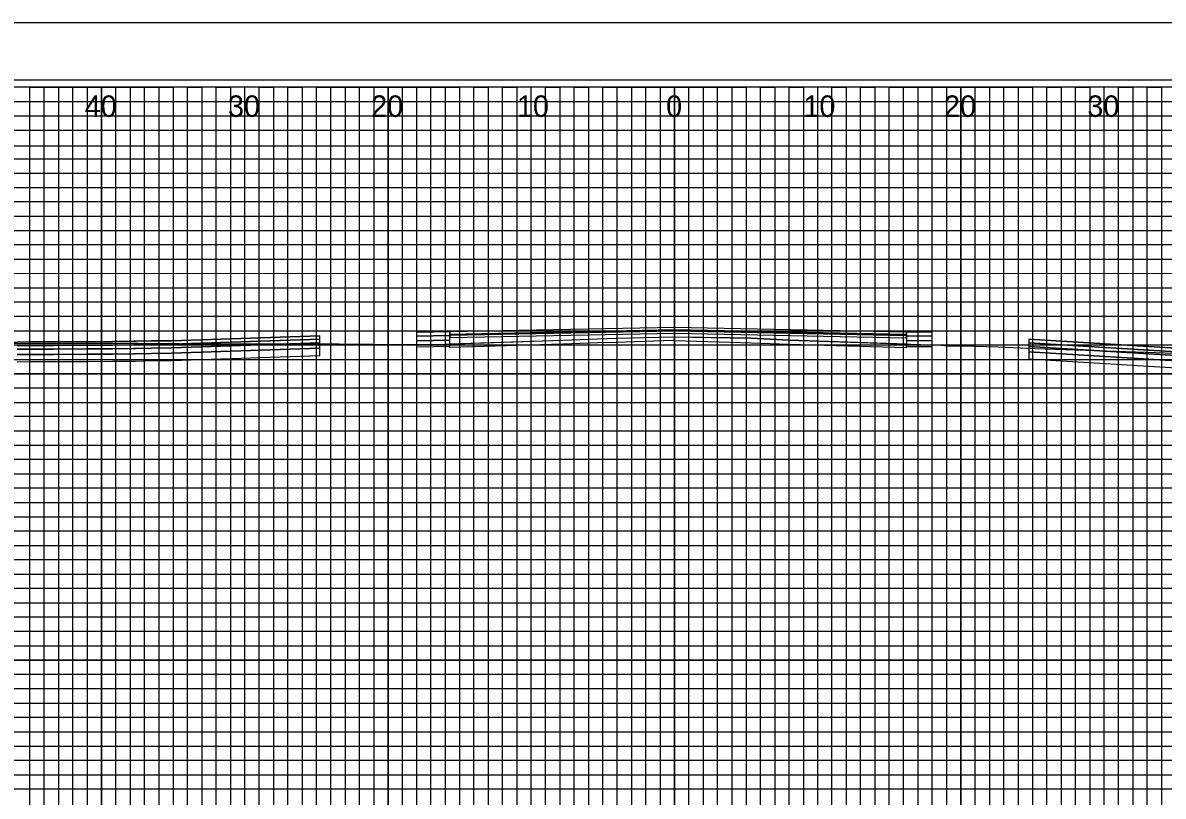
# Model space of a CAD drawing. Extents: x -13 to 760, y -5 to 1491.
# Drawn here: x 114.5 to 194.1, y 1436.5 to 1490.5 of the extents above; entities that cross this region are included whole.
import ezdxf

# ---------------------------------------------------------------- set-up
doc = ezdxf.new("R2010")
doc.units = 0
for name, color, linetype in [('Exist XS Ground Line', 7, 'Continuous'), ('Prop CMT Concrete Structures', 7, 'Continuous'), ('Prop CMT Pvmt Course 1', 7, 'Continuous'), ('Prop CMT Pvmt Course 2', 7, 'Continuous'), ('Prop CMT Pvmt Course 3', 7, 'Continuous'), ('Prop CMT Pvmt Course 4', 7, 'Continuous'), ('Prop CMT Subgrade Earthwork', 7, 'Continuous'), ('Prop Corridor Mesh Bottom', 7, 'Continuous'), ('Prop XS Offset Labels', 7, 'Continuous'), ('Scratch_Level_6', 7, 'Continuous'), ('Scratch_Level_9', 7, 'Continuous'), ('Sheet Cross Section CELL', 7, 'Continuous'), ('Sheet Cross Section Grid Major CELL', 7, 'Continuous'), ('Sheet Cross Section Grid Middle CELL', 7, 'Continuous'), ('Sheet Cross Section Grid Minor 1 CELL', 7, 'Continuous'), ('Sheet Cross Section Grid Minor 2 CELL', 7, 'Continuous'), ('Sheet Cutting Line CELL', 7, 'Continuous'), ('Sheet DOT Grid CELL', 7, 'Continuous'), ('Sheet Plot Border Inside CELL', 7, 'Continuous'), ('Sheet Plot Border Outside CELL', 7, 'Continuous')]:
    doc.layers.add(name, color=color, linetype=linetype)

msp = doc.modelspace()

# ---------------------------------------------------------------- linework, layer by layer
at = {"layer": 'Exist XS Ground Line'}
msp.add_lwpolyline([(106.336, 1468.112), (118.955, 1468.147), (122.535, 1468.157), (128.384, 1468.107), (132.28, 1468.115), (133.801, 1468.109), (136.596, 1468.114), (141.303, 1468.066), (143.958, 1468.089), (152.205, 1468.367), (154.623, 1468.457), (155.921, 1468.491), (159.879, 1468.583), (163.881, 1468.525), (165.361, 1468.5), (168.016, 1468.365), (178.623, 1468.013), (179.044, 1467.964), (180.183, 1467.974), (182.593, 1467.894), (185.157, 1467.784), (190.145, 1467.622), (197.718, 1467.361)], dxfattribs=at)
msp.add_lwpolyline([(106.336, 1468.112), (118.955, 1468.147), (122.535, 1468.157), (128.384, 1468.107), (132.28, 1468.115), (133.801, 1468.109), (136.596, 1468.114), (141.303, 1468.066), (143.958, 1468.089), (152.205, 1468.367), (154.623, 1468.457), (155.921, 1468.491), (159.879, 1468.583), (163.881, 1468.525), (165.361, 1468.5), (168.016, 1468.365), (178.623, 1468.013), (179.044, 1467.964), (180.183, 1467.974), (182.593, 1467.894), (185.157, 1467.784), (190.145, 1467.622), (197.718, 1467.361)], dxfattribs=at)
at = {"layer": 'Prop CMT Pvmt Course 1'}
for points in [[(144.313, 1468.934), (144.313, 1468.768), (160, 1469.082), (160, 1469.082), (176.202, 1468.757), (176.202, 1468.757), (176.202, 1468.924), (176.202, 1468.924), (176.202, 1468.924), (160, 1469.248), (160, 1469.248), (144.313, 1468.934), (144.313, 1468.934)], [(114.117, 1467.98), (114.991, 1467.985), (116.643, 1467.993), (119.029, 1468.005), (120.751, 1468.017), (122.259, 1468.03), (122.363, 1468.031), (123.49, 1468.056), (124.885, 1468.073), (135.25, 1468.425), (135.25, 1468.425), (135.25, 1468.425), (135.25, 1468.675), (135.25, 1468.675), (135.25, 1468.675), (124.885, 1468.323), (123.49, 1468.306), (122.363, 1468.281), (122.259, 1468.28), (120.751, 1468.267), (119.029, 1468.255), (116.643, 1468.243), (114.991, 1468.235), (114.117, 1468.23)], [(144.313, 1468.934), (142, 1468.888), (142, 1468.888), (142, 1468.638), (144.313, 1468.684), (144.313, 1468.684), (144.313, 1468.934), (144.313, 1468.934), (144.313, 1468.934)], [(178, 1468.888), (176.202, 1468.924), (176.202, 1468.924), (176.202, 1468.674), (178, 1468.638), (178, 1468.638), (178, 1468.888), (178, 1468.888), (178, 1468.888)], [(184.75, 1468.43), (184.75, 1468.18), (184.75, 1468.18), (184.75, 1468.18), (196.182, 1467.475)], [(196.182, 1467.725), (184.75, 1468.43), (184.75, 1468.43), (184.75, 1468.43)]]:
    msp.add_lwpolyline(points, dxfattribs=at)
at = {"layer": 'Prop CMT Pvmt Course 2'}
for points in [[(144.313, 1468.768), (144.313, 1468.705), (160, 1469.019), (160, 1469.019), (176.202, 1468.695), (176.202, 1468.695), (176.202, 1468.757), (176.202, 1468.757), (176.202, 1468.757), (160, 1469.082), (160, 1469.082), (144.313, 1468.768), (144.313, 1468.768)], [(114.117, 1467.73), (114.991, 1467.735), (116.643, 1467.743), (119.029, 1467.755), (120.751, 1467.767), (122.259, 1467.78), (122.363, 1467.781), (123.49, 1467.806), (124.885, 1467.823), (135.25, 1468.175), (135.25, 1468.175), (135.25, 1468.175), (135.25, 1468.425), (135.25, 1468.425), (135.25, 1468.425), (124.885, 1468.073), (123.49, 1468.056), (122.363, 1468.031), (122.259, 1468.03), (120.751, 1468.017), (119.029, 1468.005), (116.643, 1467.993), (114.991, 1467.985), (114.117, 1467.98)], [(144.313, 1468.684), (142, 1468.638), (142, 1468.638), (142, 1468.305), (144.313, 1468.351), (144.313, 1468.351), (144.313, 1468.684), (144.313, 1468.684), (144.313, 1468.684)], [(178, 1468.638), (176.202, 1468.674), (176.202, 1468.674), (176.202, 1468.341), (178, 1468.305), (178, 1468.305), (178, 1468.638), (178, 1468.638), (178, 1468.638)], [(184.75, 1468.18), (184.75, 1467.93), (184.75, 1467.93), (184.75, 1467.93), (196.182, 1467.225)], [(196.182, 1467.475), (184.75, 1468.18), (184.75, 1468.18), (184.75, 1468.18)]]:
    msp.add_lwpolyline(points, dxfattribs=at)
at = {"layer": 'Prop CMT Pvmt Course 3'}
for points in [[(144.313, 1468.351), (142, 1468.305), (142, 1468.305), (142, 1467.889), (144.313, 1467.934), (144.313, 1467.934), (144.313, 1468.351), (144.313, 1468.351), (144.313, 1468.351)], [(144.313, 1468.705), (144.313, 1468.539), (160, 1468.852), (160, 1468.852), (176.202, 1468.528), (176.202, 1468.528), (176.202, 1468.695), (176.202, 1468.695), (176.202, 1468.695), (160, 1469.019), (160, 1469.019), (144.313, 1468.705), (144.313, 1468.705)], [(178, 1468.305), (176.202, 1468.341), (176.202, 1468.341), (176.202, 1467.924), (178, 1467.888), (178, 1467.888), (178, 1468.305), (178, 1468.305), (178, 1468.305)], [(114.117, 1467.355), (114.991, 1467.36), (116.643, 1467.368), (119.029, 1467.38), (120.751, 1467.392), (122.259, 1467.405), (122.363, 1467.406), (123.49, 1467.431), (124.885, 1467.448), (135.25, 1467.8), (135.25, 1467.8), (135.25, 1467.8), (135.25, 1468.175), (135.25, 1468.175), (135.25, 1468.175), (124.885, 1467.823), (123.49, 1467.806), (122.363, 1467.781), (122.259, 1467.78), (120.751, 1467.767), (119.029, 1467.755), (116.643, 1467.743), (114.991, 1467.735), (114.117, 1467.73)], [(184.75, 1467.93), (184.75, 1467.555), (184.75, 1467.555), (184.75, 1467.555), (196.182, 1466.85)], [(196.182, 1467.225), (184.75, 1467.93), (184.75, 1467.93), (184.75, 1467.93)]]:
    msp.add_lwpolyline(points, dxfattribs=at)
at = {"layer": 'Prop CMT Pvmt Course 4'}
for points in [[(114.117, 1466.855), (114.991, 1466.86), (116.643, 1466.868), (119.029, 1466.88), (120.751, 1466.892), (122.259, 1466.905), (122.363, 1466.906), (123.49, 1466.931), (124.885, 1466.948), (135.25, 1467.3), (135.25, 1467.3), (135.25, 1467.3), (135.25, 1467.8), (135.25, 1467.8), (135.25, 1467.8), (124.885, 1467.448), (123.49, 1467.431), (122.363, 1467.406), (122.259, 1467.405), (120.751, 1467.392), (119.029, 1467.38), (116.643, 1467.368), (114.991, 1467.36), (114.117, 1467.355)], [(184.75, 1467.555), (184.75, 1467.055), (184.75, 1467.055), (184.75, 1467.055), (196.182, 1466.35)], [(196.182, 1466.85), (184.75, 1467.555), (184.75, 1467.555), (184.75, 1467.555)]]:
    msp.add_lwpolyline(points, dxfattribs=at)
at = {"layer": 'Prop CMT Subgrade Earthwork'}
for points in [[(142, 1467.889), (144.313, 1467.934), (144.313, 1467.934)], [(178, 1467.888), (178, 1467.888), (176.202, 1467.924)]]:
    msp.add_lwpolyline(points, dxfattribs=at)
at = {"layer": 'Prop Corridor Mesh Bottom'}
for points in [[(159.879, 1468.583), (160, 1468.581), (160, 1468.581), (160, 1468.331), (159.879, 1468.327), (159.879, 1468.327), (155.921, 1468.206), (155.921, 1468.206), (154.623, 1468.166), (152.205, 1468.092), (152.205, 1468.092), (144.313, 1467.851), (144.313, 1467.851), (144.313, 1468.101), (144.313, 1468.101), (144.313, 1468.101), (152.205, 1468.367), (152.205, 1468.367), (154.623, 1468.457), (155.921, 1468.491), (155.921, 1468.491), (159.879, 1468.583), (159.879, 1468.583)], [(176.202, 1468.093), (168.016, 1468.365), (168.016, 1468.365), (165.361, 1468.5), (165.361, 1468.5), (163.881, 1468.526), (163.881, 1468.526), (160, 1468.581), (160, 1468.581), (160, 1468.581), (160, 1468.331), (160, 1468.331), (163.881, 1468.214), (163.881, 1468.214), (165.361, 1468.17), (165.361, 1468.17), (168.016, 1468.09), (168.016, 1468.09), (176.202, 1467.843), (176.202, 1467.843), (176.202, 1468.093), (176.202, 1468.093), (176.202, 1468.093)]]:
    msp.add_lwpolyline(points, dxfattribs=at)
at = {"layer": 'Scratch_Level_6'}
for points in [[(97.758, 1468.16), (101.906, 1468.181), (103.95, 1468.191), (104.095, 1468.192), (104.974, 1468.196), (108.436, 1468.213), (110.661, 1468.225), (112.404, 1468.226), (114.117, 1468.23), (114.991, 1468.235), (116.643, 1468.243), (119.029, 1468.255), (120.751, 1468.267), (122.259, 1468.28), (122.363, 1468.281), (123.49, 1468.306), (124.885, 1468.323), (135.25, 1468.675)], [(184.75, 1468.43), (184.75, 1468.43), (196.182, 1467.725)]]:
    msp.add_lwpolyline(points, dxfattribs=at)
at = {"layer": 'Sheet Cross Section CELL'}
msp.add_lwpolyline([(320, 1486.02), (0, 1486.02), (0, 1276.02), (320, 1276.02)], close=True, dxfattribs=at)
at = {"layer": 'Sheet Cross Section Grid Major CELL'}
for p, q in [((130, 1486.02), (120, 1486.02)), ((120, 1486.02), (120, 1276.02)), ((130, 1276.02), (130, 1486.02)), ((150, 1486.02), (140, 1486.02)), ((140, 1486.02), (140, 1276.02)), ((150, 1276.02), (150, 1486.02)), ((170, 1486.02), (160, 1486.02)), ((160, 1486.02), (160, 1276.02)), ((170, 1276.02), (170, 1486.02)), ((190, 1486.02), (180, 1486.02)), ((180, 1486.02), (180, 1276.02)), ((190, 1276.02), (190, 1486.02))]:
    msp.add_line(p, q, dxfattribs=at)
for points in [[(0, 1476.02), (320, 1476.02), (320, 1466.02), (0, 1466.02)], [(0, 1456.02), (320, 1456.02), (320, 1446.02), (0, 1446.02)]]:
    msp.add_lwpolyline(points, dxfattribs=at)
at = {"layer": 'Sheet Cross Section Grid Middle CELL'}
for points in [[(115, 1276.02), (115, 1486.02), (125, 1486.02), (125, 1276.02)], [(135, 1276.02), (135, 1486.02), (145, 1486.02), (145, 1276.02)], [(155, 1276.02), (155, 1486.02), (165, 1486.02), (165, 1276.02)], [(175, 1276.02), (175, 1486.02), (185, 1486.02), (185, 1276.02)], [(0, 1481.02), (275, 1481.02)], [(0, 1461.02), (320, 1461.02), (320, 1471.02), (0, 1471.02)], [(0, 1441.02), (320, 1441.02), (320, 1451.02), (0, 1451.02)]]:
    msp.add_lwpolyline(points, dxfattribs=at)
at = {"layer": 'Sheet Cross Section Grid Minor 1 CELL'}
for p, q in [((0, 1485.02), (260, 1485.02)), ((260, 1484), (0, 1484)), ((0, 1483.02), (260, 1483.02)), ((260, 1481.91), (0, 1481.91)), ((0, 1480.02), (320, 1480.02))]:
    msp.add_line(p, q, dxfattribs=at)
for points in [[(0, 1479.02), (270, 1479.02), (320, 1479.02), (320, 1478.02), (0, 1478.02)], [(0, 1477.02), (320, 1477.02), (320, 1475.02), (0, 1475.02)], [(0, 1474.02), (320, 1474.02), (320, 1473.02), (0, 1473)], [(0, 1472.02), (320, 1472.02), (320, 1470.02), (0, 1470.02)], [(0, 1469.02), (320, 1469.02), (320, 1468.02), (0, 1468.02)], [(0, 1467.02), (320, 1467.02), (320, 1465.02), (0, 1465.02)], [(0, 1464.02), (320, 1464.02), (320, 1463.02), (0, 1463.02)], [(0, 1462.02), (320, 1462.02), (320, 1460.02), (0, 1460.02)], [(0, 1459.02), (320, 1459.02), (320, 1458.02), (0, 1458.02)], [(0, 1457.02), (320, 1457.02), (320, 1455.02), (0, 1455.02)], [(0, 1454.02), (320, 1454.02), (320, 1453.02), (0, 1453.02)], [(0, 1452.02), (320, 1452.02), (320, 1449.97), (320, 1449.02), (320, 1448.02), (0, 1448.02)], [(0, 1450.02), (320, 1450.02), (320, 1449.02), (0, 1449.02)], [(0, 1447.02), (320, 1447.02), (320, 1445.02), (0, 1445.05)], [(0, 1445.05), (320, 1445.02), (320, 1444.02), (0, 1444.02)], [(0, 1443.02), (320, 1443.02), (320, 1442.02), (0, 1442.02)], [(0, 1440.02), (320, 1440.02), (320, 1439.02), (0, 1439.02)], [(0, 1438.02), (320, 1438.02), (320, 1437.02), (0, 1437.02)]]:
    msp.add_lwpolyline(points, dxfattribs=at)
at = {"layer": 'Sheet Cross Section Grid Minor 2 CELL'}
for points in [[(115, 1276.02), (116, 1276.02), (116, 1486.02), (117, 1486.02), (117, 1276.02)], [(117, 1276.02), (118, 1276.02), (118, 1486.02), (119, 1486.02), (119, 1276.02)], [(120, 1276.02), (121, 1276.02), (121, 1486.02), (122, 1486.02), (122, 1276.02)], [(122, 1276.02), (123, 1276.02), (123, 1486.02), (124, 1486.02), (124, 1276.02)], [(125, 1276.02), (126, 1276.02), (126, 1486.02), (127, 1486.02), (127, 1276.02)], [(127, 1276.02), (128, 1276.02), (128, 1486.02), (129, 1486.02), (129, 1276.02)], [(130, 1276.02), (131, 1276.02), (131, 1486.02), (132, 1486.02), (132, 1276.02)], [(132, 1276.02), (133, 1276.02), (133, 1486.02), (134, 1486.02), (134, 1276.02)], [(135, 1276.02), (136, 1276.02), (136, 1486.02), (137, 1486.02), (137, 1276.02)], [(137, 1276.02), (138, 1276.02), (138, 1486.02), (139, 1486.02), (139, 1276.02)], [(140, 1276.02), (141, 1276.02), (141, 1486.02), (142, 1486.02), (142, 1276.02)], [(142, 1276.02), (143, 1276.02), (143, 1486.02), (144, 1486.02), (144, 1276.02)], [(145, 1276.02), (146, 1276.02), (146, 1486.02), (147, 1486.02), (147, 1276.02)], [(147, 1276.02), (148, 1276.02), (148, 1486.02), (149, 1486.02), (149, 1276.02)], [(150, 1276.02), (151, 1276.02), (151, 1486.02), (152, 1486.02), (152, 1276.02)], [(152, 1276.02), (153, 1276.02), (153, 1486.02), (154, 1486.02), (154, 1276.02)], [(155, 1276.02), (156, 1276.02), (156, 1486.02), (157, 1486.02), (157, 1276.02)], [(157, 1276.02), (158, 1276.02), (158, 1486.02), (159, 1486.02), (159, 1276.02)], [(160, 1276.02), (161, 1276.02), (161, 1486.02), (162, 1486.02), (162, 1276.02)], [(162, 1276.02), (163, 1276.02), (163, 1486.02), (164, 1486.02), (164, 1276.02)], [(165, 1276.02), (166, 1276.02), (166, 1486.02), (167, 1486.02), (167, 1276.02)], [(167, 1276.02), (168, 1276.02), (168, 1486.02), (169, 1486.02), (169, 1276.02)], [(170, 1276.02), (171, 1276.02), (171, 1486.02), (172, 1486.02), (172, 1276.02)], [(172, 1276.02), (173, 1276.02), (173, 1486.02), (174, 1486.02), (174, 1276.02)], [(175, 1276.02), (176, 1276.02), (176, 1486.02), (177, 1486.02), (177, 1276.02)], [(177, 1276.02), (178, 1276.02), (178, 1486.02), (179, 1486.02), (179, 1276.02)], [(180, 1276.02), (181, 1276.02), (181, 1486.02), (182, 1486.02), (182, 1276.02)], [(182, 1276.02), (183, 1276.02), (183, 1486.02), (184, 1486.02), (184, 1276.02)], [(185, 1276.02), (186, 1276.02), (186, 1486.02), (187, 1486.02), (187, 1276.02)], [(187, 1276.02), (188, 1276.02), (188, 1486.02), (189, 1486.02), (189, 1276.02)], [(190, 1276.02), (191, 1276.02), (191, 1486.02), (192, 1486.02), (192, 1276.02)], [(192, 1276.02), (193, 1276.02), (193, 1486.02), (194, 1486.02), (194, 1276.02)]]:
    msp.add_lwpolyline(points, dxfattribs=at)
at = {"layer": 'Sheet Cutting Line CELL'}
msp.add_line((323.3, 1490.52), (-13.4, 1490.52), dxfattribs=at)
at = {"layer": 'Sheet DOT Grid CELL'}
for p, q in [((120, 1276.02), (120, 1486.02)), ((130, 1276.02), (130, 1486.02)), ((140, 1276.02), (140, 1486.02)), ((150, 1276.02), (150, 1486.02)), ((160, 1276.02), (160, 1486.02)), ((170, 1276.02), (170, 1486.02)), ((180, 1276.02), (180, 1486.02)), ((190, 1276.02), (190, 1486.02)), ((0, 1476.02), (320, 1476.02)), ((0, 1466.02), (320, 1466.02)), ((0, 1456.02), (320, 1456.02)), ((0, 1446.02), (320, 1446.02))]:
    msp.add_line(p, q, dxfattribs=at)
at = {"layer": 'Sheet Plot Border Inside CELL'}
msp.add_lwpolyline([(-10.8, 1275.52), (322.4, 1275.52), (322.4, 1486.52), (-10.8, 1486.52)], close=True, dxfattribs=at)
at = {"layer": 'Sheet Plot Border Outside CELL'}
msp.add_lwpolyline([(-13.4, 1271.52), (323.3, 1271.52), (323.3, 1490.52), (-13.4, 1490.52)], close=True, dxfattribs=at)

# ---------------------------------------------------------------- texts
at = {"layer": 'Prop CMT Concrete Structures'}
msp.add_text('X', height=0.0025, dxfattribs=at).set_placement((184.749, 1468.381))
at = {"layer": 'Prop XS Offset Labels'}
for s, p in [('40', (118.828, 1483.95)), ('30', (128.828, 1483.95)), ('20', (138.828, 1483.95)), ('10', (149.007, 1483.95)), ('0', (159.421, 1483.95)), ('0', (159.421, 1483.95)), ('10', (169.007, 1483.95)), ('20', (178.828, 1483.95)), ('30', (188.828, 1483.95))]:
    msp.add_text(s, height=1.5, dxfattribs=at).set_placement(p)
at = {"layer": 'Scratch_Level_9'}
for p in [(159.999, 1469.247), (141.999, 1468.887), (177.999, 1468.887)]:
    msp.add_text('X', height=0.0025, dxfattribs=at).set_placement(p)

doc.saveas('drawing.dxf')
